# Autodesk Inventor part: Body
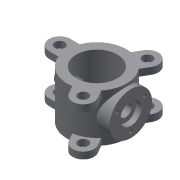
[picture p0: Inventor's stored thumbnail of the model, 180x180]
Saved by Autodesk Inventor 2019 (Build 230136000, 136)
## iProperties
Created: 2011-04
Part Number: Body
Material: Generic
Document SubType Name: Modeling
Designer: Dell
Density: 1 g/cm^3
Appearance: Default
Author: Dell
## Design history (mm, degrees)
sketch "Sketch1"
  geometry: 1 further point
sketch "Sketch2"
  geometry: C1 r 97 at (0, 0); C2 r 140 at (0, 0); 1 further point
  constraints: 2 centre point, 1 coincident
  dimensions: "d0" = 194 diameter of C1; "d1" = 280 diameter of C2
extrude "Extrusion1" new body sketch "Sketch2" stored distance "d2" = 225; taper "d3" = 0 deg
workplane "Work Plane1"
sketch "Sketch3"
  geometry: L1 (-140, 112.5)-(140, 112.5) reference; C1 r 100 at (0, 0); 1 further point
  constraints: 1 centre point, 1 coincident
  dimensions: "d5" = 200 diameter of C1; "d7" = 112.5 distance from line of point (0, 0) L1 (derived)
extrude "Extrusion2" join sketch "Sketch3" stored distance "d8" = 225; taper "d9" = 0 deg
hole "Hole1" diameter "d12" = 56; stored, may be unused: countersink angle "d16" = 90 deg, drill point angle "d18" = 118 deg; dims "d13" = 6, "d14" = 100, "d15" = 25, "d17" = 428.75, "d39" = 10, "d40" = 10
workplane "Work Plane2"
sketch "Sketch4"
  geometry: C1 r 37.5 at (0, 0); C2 r 28 at (0, 0); 1 further point
  constraints: 2 centre point, 1 coincident
  dimensions: "d20" = 75 diameter of C1; "d37" = 56 diameter of C2
sketch "Sketch5"
  geometry: L1 (130.767, -50)-(175, -50); L2 (175, 50)-(130.767, 50); C1 r 23.5 at (175, 0); A1 r 50 centre (175, 0) between (175, -50) and (175, 50); A2 r 140 centre (0, 0) between (130.767, -50) and (130.767, 50); 1 further point
  constraints: 4 end point, 4 point on circle, 3 centre point, 2 coincident
  dimensions: "d29" = 50 radius of A1 (derived); "d30" = 47 diameter of C1 (derived); "d31" = 175 distance of A1.centre point (0, 0)
extrude "Extrusion4" join sketch "Sketch5" distance "d32" = 32; taper "d33" = 0 deg
pattern_circular "Circular Pattern1" dims angle "d35" = 360 deg
mirror "Mirror1"
extrude "Extrusion5" join sketch "Sketch4" stored distance "d38" = 32; taper "d41" = 0 deg
sketch "Sketch6"
  geometry: C1 r 50 at (0, 0); C2 r 100 at (0, 0); 3 further points
  constraints: 2 centre point, 4 other
  dimensions: "d44" = 75 distance of point (75, 0) C1.centre; "d45" = 360 deg dimension on C1.centre point (75, 0) (derived)
hole "Hole2" sketch "Sketch6" at (-37.5, 64.952) diameter "d46" = 18.376; stored, may be unused: countersink angle "d50" = 90 deg, drill point angle "d52" = 118 deg; dims "d47" = 40, "d48" = 4, "d49" = 2, "d51" = 47.3
pattern_circular "Circular Pattern2" dims angle "d54" = 360 deg
body "Solid1"
other parameters: "d19" = -325
